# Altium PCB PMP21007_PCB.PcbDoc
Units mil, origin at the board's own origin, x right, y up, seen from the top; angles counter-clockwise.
Board outline 3407.03 x 1007.03 mil, 2 copper layers (Top Layer, Bottom Layer), stack 62 mil thick; 21 components, 11 nets, 43 pads, 0 vias.
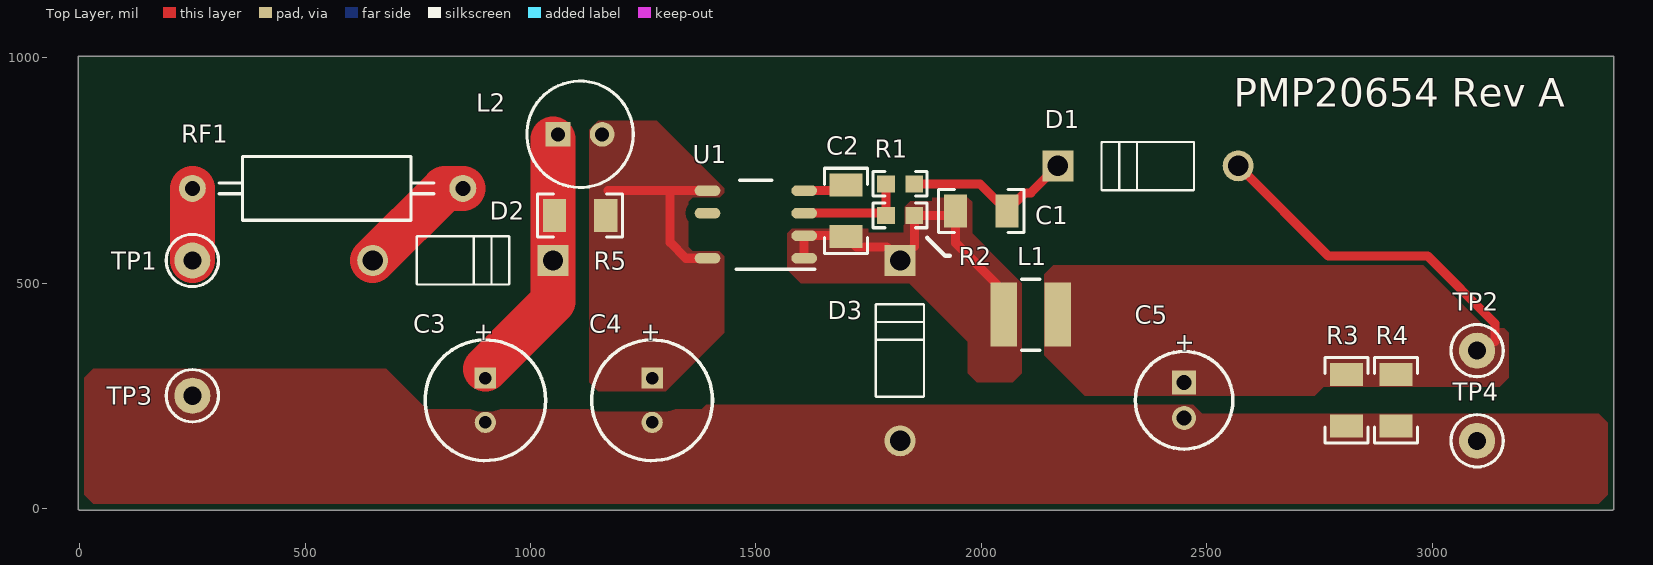
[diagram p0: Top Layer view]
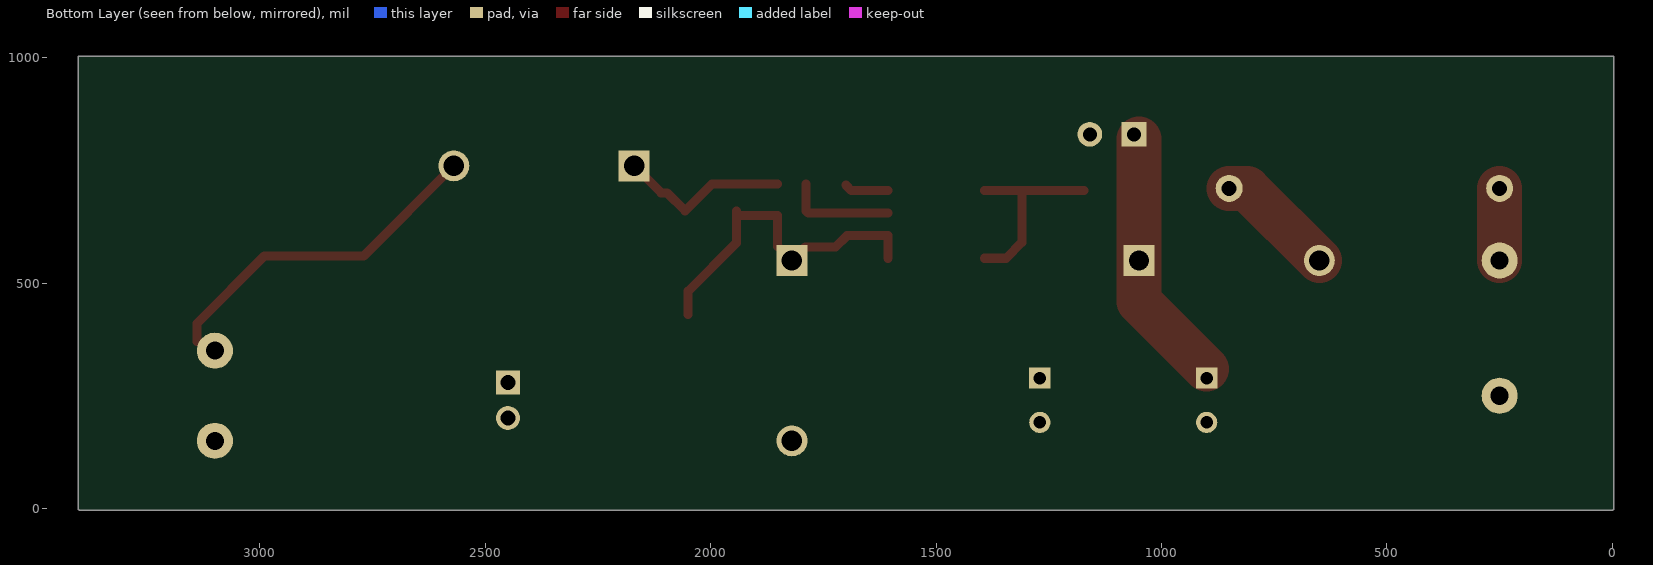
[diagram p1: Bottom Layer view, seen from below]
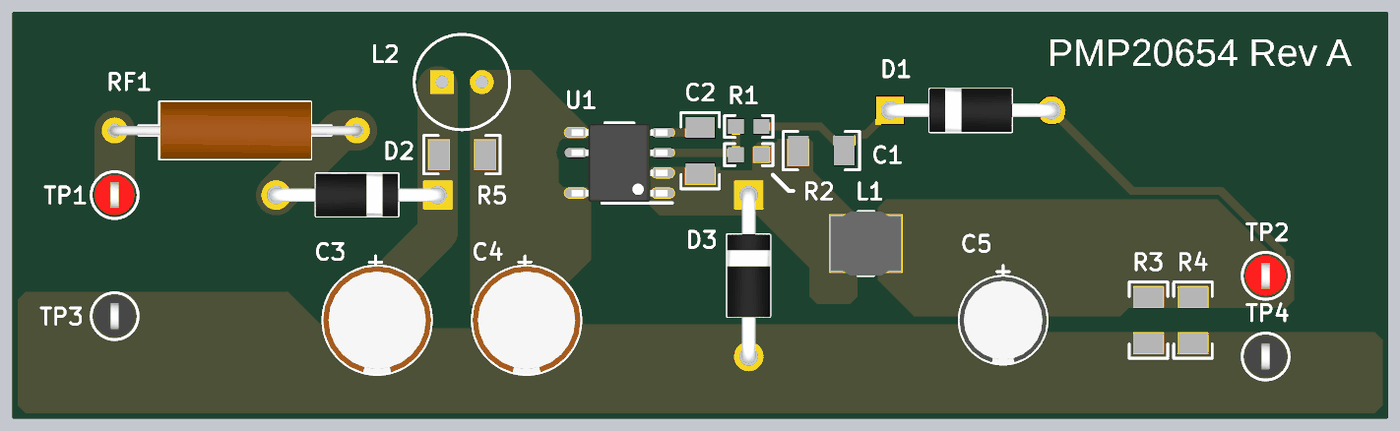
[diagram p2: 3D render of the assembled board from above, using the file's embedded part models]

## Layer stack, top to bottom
Top Solder: solder mask 0.4, Solder Resist, Dk 3.5
Top Layer: signal copper 1.4
Dielectric1: core 59.2, FR-4, Dk 4.8
Bottom Layer: signal copper 1.4
Bottom Solder: solder mask 0.4, Solder Resist, Dk 3.5

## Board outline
0,-3.52 cw(c0,0) -3.51,0 -3.51,1000 cw(c0,1000) 0,1003.51 3400,1003.51 cw(c3400,1000) 3403.51,1000 3403.51,0 cw(c3400,0) 3400,-3.52

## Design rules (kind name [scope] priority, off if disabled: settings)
AcuteAngle [All] p1: minimum=4.50000000000000E+0001 checktracksonly=FALSE
AssemblyTestPointUsage [All] p1: valid=2
Clearance Clearance_2 [InNetClass('HV') vs Not InNetClass('HV')] p1: gap=45
Clearance Clearance_Keepouts [((IsTrack Or IsArc) And Not InPoly) And IsFree and IsKeepOut vs ((IsTrack Or IsArc) And Not InPoly) And IsFree and IsKeepOut] p2: gap=0
Clearance Clearance_BoardEdge_MountingHoles [OnCopper and InComponentClass('Mounting Holes') vs IsKeepOut] p3: gap=40
Clearance Clearance_BoardEdge_Poly [OnCopper and InPoly vs IsKeepOut] p4: gap=25
Clearance Clearance_BoardEdge [OnCopper and Not InComponentClass('Logo') and not InComponentClass('FiducialMark') and not InRegion(1000,500,4000,800) and Not IsKeepout vs IsKeepOut] p5: gap=75
Clearance Clearance_Poly [InPolygon] p6: gap=20
Clearance [All] p7: gap=7.87
ComponentClearance ComponentClearance_MountingHoles_FiducialMarks [InComponentClass('Mounting Holes') vs InComponentClass('FiducialMark')] p1: gap=20 collisioncheckmode=3 verticalgap=10 showdistances=FALSE
ComponentClearance ComponentClearance_Shunt [InComponentClass('Header') vs InComponentClass('Shunt')] p2: gap=0 collisioncheckmode=3 verticalgap=0 showdistances=FALSE
ComponentClearance ComponentClearance_Logo [InComponentClass('Logo')] p3: gap=5 collisioncheckmode=3 verticalgap=10 showdistances=FALSE
ComponentClearance ComponentClearance_ScrewToNut [(HasFootprint('NY PMS 440 0025 PH')) vs (HasFootprint('Keystone_1902C'))] p4: gap=20 collisioncheckmode=3 verticalgap=100000 showdistances=FALSE
ComponentClearance ComponentClearance_MountingHoles [InComponentClass('Mounting Holes')] p5: gap=20 collisioncheckmode=3 verticalgap=10 showdistances=FALSE
ComponentClearance ComponentClearance_SmallPassives [HasFootprint('0201*') or HasFootprint('0402*') or HasFootprint('0508') or HasFootprint('0603*') or HasFootprint('0612') or HasFootprint('0805*') or HasFootprint('0815*') or HasFootprint('0830*') or HasFootprint('1206*') or HasFootprint('1210*') or HasFootprint('1808*') or HasFootprint('1812*') or HasFootprint('1825*') or HasFootprint('2010*') or HasFootprint('2220*') or HasFootprint('2225*') or HasFootprint('2512*') or HasFootprint('2728*') or HasFootprint('3518*') vs HasFootprint('0201*') or HasFootprint('0402*') or HasFootprint('0508') or HasFootprint('0603*') or HasFootprint('0612') or HasFootprint('0805*') or HasFootprint('0815*') or HasFootprint('0830*') or HasFootprint('1206*') or HasFootprint('1210*') or HasFootprint('1808*') or HasFootprint('1812*') or HasFootprint('1825*') or HasFootprint('2010*') or HasFootprint('2220*') or HasFootprint('2225*') or HasFootprint('2512*') or HasFootprint('2728*') or HasFootprint('3518*')] p6: gap=20 collisioncheckmode=3 verticalgap=20 showdistances=FALSE
ComponentClearance ComponentClearance_THtoSMT [IsThruComponent vs IsSMTComponent] p7: gap=10 collisioncheckmode=3 verticalgap=10 showdistances=FALSE
ComponentClearance ComponentClearance_THtoTH [IsThruComponent vs IsThruComponent] p8: gap=10 collisioncheckmode=3 verticalgap=10 showdistances=FALSE
ComponentClearance [All] p9: gap=10 collisioncheckmode=3 verticalgap=10 showdistances=FALSE
DiffPairsRouting [All] p1: maxlimit=100 minlimit=10 mostfreqgap=10 toplayer_minwidth=15 toplayer_maxwidth=15 toplayer_prefwidth=15 bottomlayer_minwidth=15 bottomlayer_maxwidth=15 bottomlayer_prefwidth=15 maxuncoupledlength=1000
FabricationTestPointUsage TestPointUsage [All] p1: valid=2 allowmultiple=FALSE
FabricationTestpoint Testpoint [All] p1: side=3 testpointundercomponent=TRUE minsize=40 maxsize=100 preferedsize=60 minholesize=0 maxholesize=40 preferedholesize=32 testpointgrid=1 allowsidetop=TRUE allowsidebottom=TRUE usegrid=TRUE gridtolerance=0.01
FanoutControl Fanout_LCC [IsLCC] p1: bgadir=Out bgaviamode=Centered fanoutstyle=Auto fanoutdirection=Alternating viagrid=1 // Fanout_LCC (Default Rule)
FanoutControl Fanout_BGA [IsBGA] p2: bgadir=Out bgaviamode=Centered fanoutstyle=Auto fanoutdirection=Alternating viagrid=1 // Fanout_BGA (Default Rule)
FanoutControl Fanout_Default [All] p4: bgadir=Out bgaviamode=Centered fanoutstyle=Auto fanoutdirection=Alternating viagrid=1 // Fanout_Default (Default Rule)
FanoutControl Fanout_Small [(CompPinCount < 5)] p5: bgadir=Out bgaviamode=Centered fanoutstyle=Auto fanoutdirection=OutThenIn viagrid=1 // Fanout_Small (Default Rule)
Height [All] p1: minheight=0 maxheight=3000 prefheight=500
HoleSize [All] p1: absolutevalues=TRUE maxlimit=251 minlimit=7 maxpercent=80.000 minpercent=20.000
MinimumAnnularRing MinimumAnnularRing_ThermalPadVias [IsVia and InAnyComponent] p1: minimumring=5.91
MinimumAnnularRing [All] p2: minimumring=4.9
MinimumSolderMaskSliver MinimumSolderMaskSliver_Logo [InComponentClass('Logo') vs InComponentClass('Logo')] p1: minsoldermaskwidth=0.7
MinimumSolderMaskSliver [All] p2: minsoldermaskwidth=2
PlaneConnect [All] p1: planeconnectstyle=Relief reliefexpansion=10 reliefentries=4 reliefconductorwidth=10 reliefairgap=10
PolygonConnect PolygonConnect_10 [All vs IsNamedPolygon('GND') Or  IsNamedPolygon('C1_2') Or  IsNamedPolygon('C4_1') Or  IsNamedPolygon('C5_1')] p1: connectstyle=Direct reliefconductorwidth=10 reliefentries=4 polygonreliefangle="90 Angle" airgapwidth=10
PolygonConnect PolygonConnect_9 [All vs IsNamedPolygon('C11_1') Or  IsNamedPolygon('Vin') Or  IsNamedPolygon('Vin') Or  IsNamedPolygon('5V') Or  IsNamedPolygon('D6_2') Or  IsNamedPolygon('Q3_3') Or  IsNamedPolygon('GND2') Or  IsNamedPolygon('GND2') Or  IsNamedPolygon('GND') Or  IsNamedPolygon('Q3_4') Or  IsNamedPolygon('12V5') Or  IsNamedPolygon('GND') Or  IsNamedPolygon('12V5') Or  IsNamedPolygon('D3_1')] p2: connectstyle=Direct reliefconductorwidth=10 reliefentries=4 polygonreliefangle="90 Angle" airgapwidth=10
PolygonConnect PolygonConnect_8 [All vs IsNamedPolygon('C11_1') Or  IsNamedPolygon('Vin') Or  IsNamedPolygon('12V5') Or  IsNamedPolygon('Q3_3') Or  IsNamedPolygon('GND2') Or  IsNamedPolygon('GND2') Or  IsNamedPolygon('5V') Or  IsNamedPolygon('Q3_4') Or  IsNamedPolygon('12V5')] p3: connectstyle=Direct reliefconductorwidth=10 reliefentries=4 polygonreliefangle="90 Angle" airgapwidth=10
PolygonConnect PolygonConnect_7 [All vs IsNamedPolygon('GND2') Or  IsNamedPolygon('GND2') Or  IsNamedPolygon('5V') Or  IsNamedPolygon('12V5') Or  IsNamedPolygon('12V5') Or  IsNamedPolygon('C11_1')] p4: connectstyle=Direct reliefconductorwidth=10 reliefentries=4 polygonreliefangle="90 Angle" airgapwidth=10
PolygonConnect PolygonConnect_6 [All vs IsNamedPolygon('GND2') Or  IsNamedPolygon('SGND') Or  IsNamedPolygon('GND1') Or  IsNamedPolygon('C901_1') Or  IsNamedPolygon('SGND') Or  IsNamedPolygon('GND2') Or  IsNamedPolygon('GND1')] p5: connectstyle=Direct reliefconductorwidth=10 reliefentries=4 polygonreliefangle="90 Angle" airgapwidth=10
PolygonConnect PolygonConnect_5 [All vs IsNamedPolygon('GND1') Or  IsNamedPolygon('GND1')] p6: connectstyle=Direct reliefconductorwidth=10 reliefentries=4 polygonreliefangle="90 Angle" airgapwidth=10
PolygonConnect PolygonConnect_4 [All vs IsNamedPolygon('C21_1') Or  IsNamedPolygon('C5_1') Or  IsNamedPolygon('C12_2') Or  IsNamedPolygon('C2_2') Or  IsNamedPolygon('C13_1') Or  IsNamedPolygon('C28_1') Or  IsNamedPolygon('C6_1') Or  IsNamedPolygon('GND') Or  IsNamedPolygon('GND2') Or  IsNamedPolygon('C14_1') Or  IsNamedPolygon('C13_1') Or  IsNamedPolygon('Q1_3') Or  IsNamedPolygon('C14_1') Or  IsNamedPolygon('C5_1') Or  IsNamedPolygon('GND2') Or  IsNamedPolygon('C28_1') Or  IsNamedPolygon('D5_2') Or  IsNamedPolygon('D6_2') Or  IsNamedPolygon('D2_1') Or  IsNamedPolygon('C12_2') Or  IsNamedPolygon('D2_1') Or  IsNamedPolygon('C4_1') Or  IsNamedPolygon('C4_1') Or  IsNamedPolygon('C2_2') Or  IsNamedPolygon('GND') Or  IsNamedPolygon('C33_1') Or  IsNamedPolygon('C9_1')] p7: connectstyle=Direct reliefconductorwidth=10 reliefentries=4 polygonreliefangle="90 Angle" airgapwidth=10
PolygonConnect PolygonConnect_3 [All vs IsNamedPolygon('C28_1') Or  IsNamedPolygon('C12_2') Or  IsNamedPolygon('C28_1') Or  IsNamedPolygon('C9_1') Or  IsNamedPolygon('D5_2') Or  IsNamedPolygon('C12_2') Or  IsNamedPolygon('C2_2') Or  IsNamedPolygon('C14_1') Or  IsNamedPolygon('C4_1') Or  IsNamedPolygon('C14_1') Or  IsNamedPolygon('D6_2') Or  IsNamedPolygon('GND2') Or  IsNamedPolygon('Q1_3') Or  IsNamedPolygon('C5_1') Or  IsNamedPolygon('D2_1') Or  IsNamedPolygon('C4_1') Or  IsNamedPolygon('C13_1') Or  IsNamedPolygon('C5_1') Or  IsNamedPolygon('C13_1') Or  IsNamedPolygon('C33_1') Or  IsNamedPolygon('D2_1') Or  IsNamedPolygon('GND') Or  IsNamedPolygon('GND') Or  IsNamedPolygon('GND2') Or  IsNamedPolygon('C2_2') Or  IsNamedPolygon('C6_1') Or  IsNamedPolygon('C21_1')] p8: connectstyle=Direct reliefconductorwidth=10 reliefentries=4 polygonreliefangle="90 Angle" airgapwidth=10
PolygonConnect PolygonConnect_2 [All vs IsNamedPolygon('C21_1') Or  IsNamedPolygon('C4_1') Or  IsNamedPolygon('D5_2') Or  IsNamedPolygon('C5_1') Or  IsNamedPolygon('C14_1') Or  IsNamedPolygon('C13_1') Or  IsNamedPolygon('C4_1') Or  IsNamedPolygon('C33_1') Or  IsNamedPolygon('C12_2') Or  IsNamedPolygon('D2_1') Or  IsNamedPolygon('C2_2') Or  IsNamedPolygon('C28_1') Or  IsNamedPolygon('C12_2') Or  IsNamedPolygon('D2_1') Or  IsNamedPolygon('C5_1') Or  IsNamedPolygon('Q1_3') Or  IsNamedPolygon('GND') Or  IsNamedPolygon('D6_2') Or  IsNamedPolygon('C6_1') Or  IsNamedPolygon('C2_2') Or  IsNamedPolygon('C14_1') Or  IsNamedPolygon('C28_1') Or  IsNamedPolygon('C13_1') Or  IsNamedPolygon('C9_1') Or  IsNamedPolygon('GND')] p9: connectstyle=Direct reliefconductorwidth=10 reliefentries=4 polygonreliefangle="90 Angle" airgapwidth=10
PolygonConnect PolygonConnect_1 [All vs IsNamedPolygon('C28_1') Or  IsNamedPolygon('D5_2') Or  IsNamedPolygon('C5_1') Or  IsNamedPolygon('C5_1') Or  IsNamedPolygon('D2_1') Or  IsNamedPolygon('C21_1') Or  IsNamedPolygon('C9_1') Or  IsNamedPolygon('C4_1') Or  IsNamedPolygon('C14_1') Or  IsNamedPolygon('C28_1') Or  IsNamedPolygon('C6_1') Or  IsNamedPolygon('C12_2') Or  IsNamedPolygon('C33_1') Or  IsNamedPolygon('C4_1') Or  IsNamedPolygon('C13_1') Or  IsNamedPolygon('C12_2') Or  IsNamedPolygon('D6_2') Or  IsNamedPolygon('C2_2') Or  IsNamedPolygon('C14_1') Or  IsNamedPolygon('D2_1') Or  IsNamedPolygon('C2_2') Or  IsNamedPolygon('C13_1')] p10: connectstyle=Direct reliefconductorwidth=10 reliefentries=4 polygonreliefangle="90 Angle" airgapwidth=10
PolygonConnect [All] p11: connectstyle=Relief reliefconductorwidth=10 reliefentries=4 polygonreliefangle="90 Angle" airgapwidth=10
RoutingVias ThermalPadVias [IsVia and InAnyComponent] p1: holewidth=7.87 width=19.68 viastyle="Through Hole" minholewidth=7.87 minwidth=19.68 maxholewidth=12.99 maxwidth=23.62
RoutingVias [All] p2: holewidth=16 width=34 viastyle="Through Hole" minholewidth=7.87 minwidth=20 maxholewidth=40 maxwidth=65
SilkToBoardRegionClearance [Not ((IsComment or IsDesignator) And (Hide <> 'False')) and not InRegion(1000,500,4000,800)] p1:
SilkToSilkClearance SilkToSilkClearance_Pb-FreeLogo [(HasFootprint('Pb-Free_Overlay_Medium') OR HasFootprint('Pb-Free_Overlay_Small')) vs (HasFootprint('Pb-Free_Overlay_Medium') OR HasFootprint('Pb-Free_Overlay_Small'))] p1: silktosilkclearance=0
SilkToSilkClearance [All] p2: silktosilkclearance=1
SilkToSolderMaskClearance "Silk to Solder Mask Opening" [All] p1: minsilkscreentomaskgap=1 clearancetoexposedcopper=FALSE
SolderMaskExpansion [All] p1: expansion=1.97
Width [All] p1: maxlimit=100 minlimit=6 preferedwidth=10 checkconnectedcopper=TRUE
14 further rules are at their usual default settings.

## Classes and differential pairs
net class HV: NC NetC1_1 NetC1_2 NetC2_1 NetC3_1 NetC4_1 NetD2_2 NetR1_1 NetRF1_2

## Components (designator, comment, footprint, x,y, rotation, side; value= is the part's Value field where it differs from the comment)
C1 "12065C104JAT2A" 1206 2000,660 r180 top
C2 "12065C223KAT2A" 1206 1700,660 r270 top
C3 "UPS2E010MED1TD" Chemi-Con_630x1150 900,240 r270 top
C4 "UPS2E010MED1TD" Chemi-Con_630x1150 1270,240 r270 top
C5 "ECA-1CHG470" NHG_500x1100 2450,240 r270 top
D1 "MUR160GP-TP" DO-41 2370,760 r0 top
D2 "1N4004" DO-41 850,550 r180 top
D3 "MUR160GP-TP" DO-41 1820,350 r270 top
L1 "SRN4018-221M" SRN4018 2110,430 r0 top
L2 "7447462102" WE-TI_5075 1110,830 r0 top
R1 "RC0603FR-07110KL" 0603 1820,720 r0 top
R2 "CRCW060310K0FKEA" 0603 1820,650 r180 top
R3 "CRCW120612K0JNEA" 1206 2810,240 r90 top
R4 "CRCW120612K0JNEA" 1206 2920,240 r90 top
R5 "CRCW12064R70JNEA" 1206 1110,650 r0 top
RF1 "FKN1WSJR-52-4R7" RESAD1524W55L900D150 550,710 r180 top
TP1 "5000" Keystone5000 250,550 r0 top
TP2 "5000" Keystone5000 3100,350 r0 top
TP3 "5001" Keystone5001 250,250 r0 top
TP4 "5001" Keystone5001 3100,150 r0 top
U1 "UCC28880DR" D0007A_N 1500,630 r180 top

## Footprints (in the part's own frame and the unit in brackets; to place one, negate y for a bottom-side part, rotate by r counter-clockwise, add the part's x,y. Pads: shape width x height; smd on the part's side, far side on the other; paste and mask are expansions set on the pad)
0603 [mm] "0603 from SM-752 data"
  rect 1x0.95 smd: 1(-0.8,0) 2(0.8,0)
  silkscreen extent -1.52,-0.69 1.52,0.69, body extent -0.87,-0.47 0.87,0.47, height 1
1206 [mm] "1206 from SM-752 data"
  rect 1.3x1.85 smd: 1(-1.45,0) 2(1.45,0)
  silkscreen extent -2.4,-1.21 2.4,1.21, body extent -1.7,-0.9 1.7,0.9, height 1.35
Chemi-Con_630x1150 [mm] "TH, 2-Leads, Dia 6.3mm, Pin Spacing 2.5mm"
  rect 1.2x1.2 hole 0.7: 1(-1.25,0)
  round 1.2 hole 0.7: 2(1.25,0)
  silkscreen extent -3.4,-3.4 3.4,3.4, body extent -3.4,-3.4 3.41,3.4, height 13.01
D0007A_N [mm] "SOIC, 7-Leads, Body 4.9x3.9mm, Pitch 1.27mm, IPC Medium Density"
  oval 1.45x0.6 smd: 1(-2.725,1.905) 2(-2.725,0.635) 3(-2.725,-0.635) 4(-2.725,-1.905) 5(2.725,-1.905) 6(2.725,-0.635) 8(2.725,1.905)
  silkscreen extent -3.32,-2.5 1.1,2.52, body extent -3.01,-2.45 3.01,2.45, height 1.75
DO-41 [mm] "diode"
  rect 1.75x1.75 hole 1.15: 1(-5.08,0)
  round 1.75 hole 1.15: 2(5.08,0)
  silkscreen extent -2.62,-1.37 2.59,1.35, body extent -5.51,-1.36 5.51,1.36, height 2.72
Keystone5000 [mil] "For Keystone 500x miniature loop terminals"
  round 80 hole 40: 1(0,0)
  silkscreen extent -58,-58 58,58, body extent -49,-49 49,49, height 182
Keystone5001 [mil] "For Keystone 500x miniature loop terminals"
  round 80 hole 40: 1(0,0)
  silkscreen extent -58,-58 58,58, body extent -49,-49 49,49, height 182
NHG_500x1100 [mm] "TH, 2-Leads, Dia 5mm,  Lead Spacing 2mm"
  rect 1.35x1.35 hole 0.85: 1(-1,0)
  round 1.35 hole 0.85: 2(1,0)
  silkscreen extent -2.75,-2.75 2.75,2.75, body extent -2.73,-2.75 2.75,2.75, height 12.51
RESAD1524W55L900D150 [mil]
  round 60 hole 33.46: 1(-300,0) 2(300,0)
  silkscreen extent -236,-71 240,71, body extent -312,-71 312,71, height 141
SRN4018 [mm] "SMD, 2-Leads, Body 4.2x4.2mm, Pitch 3.05mm"
  rect 1.5x3.6 smd: 1(-1.525,0) 2(1.525,0)
  silkscreen extent -0.5,-2 0.5,2, body extent -2.2,-2 2.2,2, height 1.8
WE-TI_5075 [mm] "Wurth WE-TI 5075"
  rect 1.4x1.4 hole 0.787: 1(-1.25,0)
  round 1.4 hole 0.787: 2(1.25,0)
  silkscreen extent -3,-3 3,3, body extent -3,-3 3,3, height 8.5

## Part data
C1: "CAP, CERM, 0.1uF, 50V, +/-5%, X7R, 1206"
C2: "CAP, CERM, 0.022uF, 50V, +/-10%, X7R, 1206"
C3 C4: library part ELXZ100ELL221MFB5D, "1µF 250V Aluminum Capacitors Radial, Can 2000 Hrs @ 105°C"
C5: "CAP, AL, 47 µF, 16 V, +/- 20%, TH"
D1 D3: library part 1N4007, "Diode Standard 600V 1A Through Hole DO-41"
D2: library part 1N4007, "Diode Standard 400V 1A Through Hole DO-41"
L1: library part SRN4018-151M, "220µH Shielded Wirewound Inductor 280mA 3.552 Ohm Max Nonstandard"
L2: "Inductor, Unshielded Drum Core, Ferrite, 1 mH, 0.25 A, 4.38 ohm, TH"
R1: "RES, 110 k, 1%, 0.1 W, 0603"
R2: "RES, 10.0k ohm, 1%, 0.1W, 0603"
R3 R4: "RES, 12k ohm, 5%, 0.25W, 1206"
R5: "RES, 4.7, 5%, 0.25 W, 1206"
RF1: "RES, 4.7 ohm, 5%, 1W, Fusible, TH"
TP1 TP2: "Test Point, Miniature, Red, TH"
TP3 TP4: "Test Point, Miniature, Black, TH"
U1: "700-V Lowest Quiescent Current Off-Line Switcher, D0007A (SOIC-7)"

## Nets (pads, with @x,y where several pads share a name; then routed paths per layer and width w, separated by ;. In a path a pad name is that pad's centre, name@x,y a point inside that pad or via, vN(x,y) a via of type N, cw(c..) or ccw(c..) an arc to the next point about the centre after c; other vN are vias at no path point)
GND: C3.2 C4.2 C5.2 D3.2 R3.1 R4.1 TP3.1 TP4.1
NC: U1.6
NetC1_1: C1.1 D1.1 R1.2 | length 384.8
  Top Layer w20: R1.2 1997.09,720 C1.1 2097.09,700 2110,700 D1.1
NetC1_2: C1.2 C2.2 D3.1 L1.1 R2.1 U1.1 U1.2 | length 754.3
  Top Layer w20: U1.1 U1.2 1697.91,605 C2.2 1722.91,580 1790,580 D3.1 1851.5,581.5 R2.1 C1.2@1932.91,650 ; C1.2 1942.91,589.22 2049.96,482.18 L1.1
NetC2_1: C2.1 U1.4 | length 97.7
  Top Layer w20: U1.4 1687.91,705 C2.1
NetC3_1: C3.1 D2.1 L2.1 R5.1 | length 571.9
  Top Layer w100: C3.1@900,309.41 1050,459.41 D2.1 L2.1@1050,819.21
NetC4_1: C4.1 L2.2 R5.2 U1.5 U1.8 | length 433.5
  Top Layer w20: 1172.09,705 1310,705 ; U1.8 1345,555 1310,590 1310,626.5 1309.17,627.33 1309.17,683.5 1310,684.33 1310,705 ; U1.5 1310,705
NetC5_1: C5.1 D1.2 L1.2 R3.2 R4.2 TP2.1 | length 755
  Top Layer w20: D1.2 2770,560 2990,560 3140,410 3140,370
NetD2_2: D2.2 RF1.1 | length 266.3
  Top Layer w100: D2.2 810,710 RF1.1
NetR1_1: R1.1 R2.2 U1.3 | length 243.3
  Top Layer w20: U1.3 1783.5,655 1788.5,660 R1.1
NetRF1_2: RF1.2 TP1.1 | length 160
  Top Layer w100: TP1.1 RF1.2

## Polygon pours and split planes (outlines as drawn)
GND on Top Layer "GND" (solid, remove dead copper, pour order 6): 30,310 10,290 10,30 30,10 130,10 3370,10 3390,30 3390,90 3390,190 3370,210 3350,210 2490,210 2470,230 2460,230 1390,230 1380,220 1340,220 770,220 680,310
NetC5_1 on Top Layer "C5_1" (solid, remove dead copper, pour order 4): 2160,540 2140,520 2140,480 2140,340 2230,250 2260,250 2740,250 2760,270 2980,270 3150,270 3170,290 3170,310 3170,390 3160,400 3120,400 2980,540
NetC1_2 on Top Layer "C1_2" (solid, remove dead copper, pour order 2): 1580,620 1570,610 1570,530 1580,520 1600,500 1790,500 1840,500 1970,370 1970,300 1990,280 2070,280 2090,300 2090,380 2090,500 2050,540 1980,610 1980,680 1970,690 1890,690 1851.3,690 1830,668.7 1830,631.3 1830,630 1820,620
NetC4_1 on Top Layer "C4_1" (solid, remove dead copper, pour order 0): 1150,860 1130,840 1130,720 1130,620 1130,520 1130,280 1150,260 1300,260 1420,380 1430,390 1430,559.29 1419.29,570 1400,570 1360,570 1350,580 1350,660 1350,680 1360,690 1370,690 1420,690 1430,700 1430,710 1280,860

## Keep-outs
Keep-Out Layer:
  text ".Layer_Name" at 577,-858.49 h60

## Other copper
Top Layer:
  text ".Layer_Name" at 577,-858.49 h60
Bottom Layer:
  text ".Layer_Name" at 577,-858.49 h60

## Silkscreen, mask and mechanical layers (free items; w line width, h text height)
Top Overlay:
  lines w10: 1880,600 1920,560 1930,560
  text "PMP20654 Rev A" at 2560,870 h108.27
  text ".Layer_Name" at 577,-858.49 h60
Bottom Overlay:
  text ".Layer_Name" at 577,-858.49 h60
Top Paste:
  text ".Layer_Name" at 577,-858.49 h60
Bottom Paste:
  text ".Layer_Name" at 577,-858.49 h60
Top Solder:
  text ".Layer_Name" at 577,-858.49 h60
  text ".Layer_Name" at 577,-858.49 h60
Bottom Solder:
  text ".Layer_Name" at 577,-858.49 h60
Drill Guide:
  text ".Layer_Name" at 577,-858.49 h60
M1 Board Outline:
  lines w7: 0,0 0,1000 ; 0,0 3400,0 ; 0,0 0,1000 ; 0,0 3400,0 ; 0,1000 3400,1000 ; 0,1000 3400,1000 ; 3400,0 3400,1000 ; 3400,0 3400,1000
  text ".Layer_Name" at 577,-858.49 h60
M2 Board Dimensions:
  rectangle: 0,-275 125,-150
  rectangle: 125,-400 500,-275
  lines w7: 0,-275 1000,-275 ; 125,-400 125,-150 ; 250,-400 250,-150 ; 500,-400 500,-150 ; 750,-400 750,-150 ; 0,-400 1000,-400 1000,-150 0,-150 0,-400
  text ".Layer_Name" at 577,-858.49 h60
M3 3D STEP Top:
  text ".Layer_Name" at 577,-858.49 h60
M4 3D STEP Bottom:
  text ".Layer_Name" at 577,-858.49 h60
M5 Assembly Top:
  lines w10: -292,-930.17 6308,-930.17 ; -292,-726.83 6310,-726.83 ; -292,-523.5 -292,-1133.5 3713,-1133.5 6310,-1133.5 6310,-523.5 -291.5,-523.5 -291.5,-1133.5 1284,-1133.5 ; 2173,-1133.5 2173,-523.5 ; 3440,-726.83 3440,-523.5 ; 4280,-726.83 4280,-523.5 ; 4902,-1140 4902,-937.17
  text "COMPONENTS MARKED 'DNP' SHOULD NOT BE POPULATED." at 1153.5,-318.5 h60
  text "ASSEMBLY VARIANT:" at 1153,-434 h60
  text ".VariantName" at 2189,-434 h60
  text "PCB VIEWED FROM TOP SIDE" at -228.5,-655.67 h60
  text "BOARD #:" at 2248,-655.67 h60
  text ".PRJ_Number" at 2793.5,-655.67 h60
  text "REV:" at 3638,-655.67 h60
  text ".PCB_Rev" at 3929.5,-655.67 h60
  text "SVN REV:" at 4476,-655.67 h60
  text ".VersionControl_RevNumber" at 4982,-655.67 h60
  text "TID #:" at 2248,-859 h60
  text ".TID" at 2793.5,-859 h60
  text "PLOT NAME =" at -228.5,-1064.34 h60
  text ".plot_File_Name" at 577,-1064.34 h60
  text "GENERATED    :" at 2250,-1064.34 h60
  text ".Print_Date" at 3119.5,-1064.34 h60
  text ".Print_Time" at 3848.5,-1064.34 h60
  text "TEXAS INSTRUMENTS" at 5113,-1064.34 h60
M6 Assembly Bottom:
  lines w10: -292.5,-727.33 6309.5,-727.33 ; -290.5,-930.67 6309.5,-930.67 ; 1115.5,-1140.5 1115.5,-937.67 ; 1737.5,-727.33 1737.5,-524 ; 2577.5,-727.33 2577.5,-524 ; 3844.5,-1134 3844.5,-524 ; 4733.5,-1134 6309,-1134 6309,-524 -292.5,-524 -292.5,-1134 2304.5,-1134 6309.5,-1134 6309.5,-524
  text "COMPONENTS MARKED 'DNP' SHOULD NOT BE POPULATED." at 6102,-318 h60
  text ".VariantName" at 5058,-434 h60
  text "ASSEMBLY VARIANT:" at 6097,-434 h60
  text ".VersionControl_RevNumber" at 1035.5,-656.17 h60
  text "SVN REV:" at 1541.5,-656.17 h60
  text ".PCB_Rev" at 2088,-656.17 h60
  text "REV:" at 2379.5,-656.17 h60
  text ".PRJ_Number" at 3224,-656.17 h60
  text "BOARD #:" at 3769.5,-656.17 h60
  text "PCB VIEWED FROM BOTTOM SIDE" at 6246,-656.17 h60
  text ".TID" at 3224,-859.5 h60
  text "TID #:" at 3769.5,-859.5 h60
  text "TEXAS INSTRUMENTS" at 904.5,-1064.84 h60
  text ".Print_Time" at 2169,-1064.84 h60
  text ".Print_Date" at 2898,-1064.84 h60
  text "GENERATED    :" at 3767.5,-1064.84 h60
  text ".plot_File_Name" at 5440.5,-1064.84 h60
  text "PLOT NAME =" at 6246,-1064.84 h60
M9 Title Sheet:
  drawing of 57 lines, arcs and shapes, not listed
  text "1" at 739.84,8036.5 h70
  text "2" at 3235.5,8036.5 h70
  text "3" at 5724.84,8036.5 h70
  text "4" at 8231.51,8036.5 h70
  text "5" at 10730.5,8036.5 h70
  text "6" at 13235.5,8036.5 h70
  text "A" at -416.5,6893.5 h70
  text "A" at 14383.5,6893.5 h70
  text "B" at -416.5,4513.5 h70
  text "B" at 14383.5,4513.5 h70
  text "C" at -416.5,2138.5 h70
  text "C" at 14383.5,2138.5 h70
  text "PROJECT TITLE:" at 11343.5,277.5 h45
  text ".PRJ_Title" at 11393.5,144.17 h70
  text "DESIGNED FOR:" at 11343.5,-23.5 h45
  text ".PRJ_Customer" at 11393.5,-163.5 h70
  text "D" at -416.5,-231.5 h70
  text "D" at 14383.5,-231.5 h70
  text "FILE NAME:" at 11343.5,-323.5 h45
  text ".PCB_File_Name_No_Path" at 11393.5,-443.5 h70
  text "Texas Instruments (TI) and/or its licensors do not warrant the accuracy or completeness of this specification" at 6374,-605.34 h45
  text "ENGINEER:" at 11343.5,-613.5 h45
  text "LAYOUT BY:" at 12848.5,-613.5 h45
  text "or any information contained therein. TI and/or its licensors do not warrant that this design will meet" at 6329.01,-718 h45
  text ".PRJ_Engineer" at 11393.5,-768.49 h70
  text ".PCB_Layout" at 12899,-768.49 h70
  text "the specifications, will be suitable for your application or fit for any particular purpose, or will operate in" at 6329.01,-830.67 h45
  text ".Layer_Name" at 577,-858.49 h60
  text "ALTIUM DESIGNER VERSION:" at 12848.5,-923.5 h45
  text "an implementation. TI and/or its licensors do not warrant that the design is production worthy. You should" at 6329.01,-943.33 h45
  text "completely validate and test your design implementation to confirm the system functionality for your application." at 6374,-1056 h45
  text ".print_Scale" at 11393.5,-1056.83 h70
  text ".Application_BuildNumber" at 12899,-1056.83 h70
  text "1" at 739.84,-1263.5 h70
  text "2" at 3235.5,-1263.5 h70
  text "3" at 5724.84,-1263.5 h70
  text "4" at 8231.51,-1263.5 h70
  text "5" at 10730.5,-1263.5 h70
  text "6" at 13235.5,-1263.5 h70
M10 Fab Notes:
  drawing of 173 lines, arcs and shapes, not listed
  text "DESIGN INFORMATION" at 12378.02,6201 h60
  text "MIN. TRACK WIDTH:" at 11733.46,6021 h60
  text "10" at 12829.7,6021 h60
  text "MIL" at 12984.46,6021 h60
  text "MIN. CLEARANCE:" at 11733.46,5889 h60
  text "0.2" at 12769.7,5889 h60
  text "mm" at 12984.46,5889 h60
  text "MIN. VIA PAD SIZE:" at 11733.46,5757 h60
  text "20" at 12799.71,5757 h60
  text "MIL" at 12984.46,5757 h60
  text "0.05mm (2MIL)" at 12428.46,5615.29 h60
  text "MINIMUM ANNULAR RING" at 11404.23,5611 h60
  text "EXTERNAL" at 13136.46,5611 h60
  text "PER" at 11604.23,5493 h60
  text "IPC-D-275 CLASS 2 LEVEL C" at 11824.23,5493 h60
  text "MIL, HOLES" at 13312.46,5380.71 h60
  text "+/-" at 12920,5380 h60
  text "+/-" at 13774,5380 h60
  text "REGISTRATION TOLERANCES:" at 11404.23,5375 h60
  text "METAL" at 12604,5375 h60
  text "5" at 13180.2,5375 h60
  text "3" at 14013.2,5375 h60
  text "MIL" at 14129.46,5375 h60
  text "+/-" at 13774,5262 h60
  text "HOLE SIZE TOLERANCE (UNLESS OTHERWISE SPECIFIED):" at 11404.23,5257 h60
  text "3" at 14013.2,5257 h60
  text "MIL" at 14129.46,5257 h60
  text "MATERIAL:" at 11329.46,5047.54 h60
  text "FR-4 High Tg" at 12315.9,4907.21 h60
  text "FR-408" at 11750.46,4898.64 h60
  text "OTHER" at 13238.46,4898.64 h60
  text "X" at 12161,4895 h60
  text "62 MIL (1.6mm) +/-10%" at 12070.56,4735.92 h60
  text "THICKNESS:" at 11404.23,4731.64 h60
  text "X" at 11942.4,4731.64 h60
  text "OTHER" at 13355.46,4731.64 h60
  text "TOLERANCE:" at 11404.23,4573.64 h60
  text "X" at 12243.53,4573.64 h60
  text "ANSI IPC-6012 TYPE 3 CLASS 2" at 12430.48,4573.64 h60
  text "OTHER +/-" at 12430.46,4417.64 h60
  text "BOW & TWIST:" at 11404.23,4260.64 h60
  text "X" at 12243.53,4260.64 h60
  text "ANSI IPC-6012 TYPE 3 CLASS 2" at 12430.48,4260.64 h60
  text "OTHER +/-" at 12430.46,4102.13 h60
  text "DRILLING:" at 11329.46,3963.64 h60
  text "REFERENCE:" at 11404.23,3846.64 h60
  text "X" at 12052.46,3846.64 h60
  text "AS SHOWN" at 12239.46,3846.64 h60
  text "X" at 12953.46,3846.64 h60
  text "NC_DRILL FILES" at 13090.46,3846.64 h60
  text "PTH COPPER THICKNESS:" at 11404.23,3688.64 h60
  text "X" at 12534.46,3688.64 h60
  text "20-30 um" at 12671.46,3688.64 h60
  text "OTHER" at 13388.46,3688.64 h60
  text "BOARD FINISH:" at 11329.46,3529.64 h60
  text "SILKSCREEN:" at 11484.68,3411.64 h60
  text "X" at 12433.46,3411.64 h60
  text "TOP" at 12559.46,3411.64 h60
  text "X" at 12943.46,3411.64 h60
  text "BOTTOM" at 13070.46,3411.64 h60
  text "SILKSCREEN COLOR:" at 11484.68,3244.64 h60
  text "X" at 12432.42,3244.64 h60
  text "WHITE" at 12559.46,3244.64 h60
  text "OTHER" at 13070.46,3244.64 h60
  text "X" at 12563.42,3085.44 h60
  text "GREEN" at 12690.46,3085.44 h60
  text "OTHER" at 13308.46,3085.44 h60
  text "SOLDER RESIST COLOR:" at 11484.68,3074.64 h60
  text "X" at 12563.42,2915.44 h60
  text "MATTE" at 12690.46,2915.44 h60
  text "SEMI-GLOSS" at 13308,2914.8 h60
  text "IMMERSION GOLD (ENIG)" at 12390.46,2726.92 h60
  text "ENEPIG" at 13728,2723.64 h60
  text "SURFACE FINISH:" at 11329.46,2722.64 h60
  text "X" at 11480,2570 h60
  text "IMM. TIN/SILVER OR EQUIV" at 11659,2565.64 h60
  text "OTHER" at 13090.46,2565.64 h60
  text "ARRAY/PANEL:" at 11329.46,2386.64 h60
  text "CUT AND TRIM PER M1 BOARD OUTLINE" at 12390.46,2382.35 h60
  text "N.C. ROUTE" at 12390.46,2230.64 h60
  text "X" at 13069.46,2230.64 h60
  text "V. SCORE" at 13256.46,2230.64 h60
  text "CERTIFICATION:" at 11329.46,2093.64 h60
  text "MATERIALS AND WORKMANSHIP FOR ALL PCBS" at 12054.46,2093.64 h60
  text "TO MEET OR EXCEED THE REQUIREMENTS OF:" at 12054.46,1995.64 h60
  text "X" at 11680.96,1859.13 h60
  text "ANSI IPC-A-600F CLASS ->" at 11819.96,1859.13 h60
  text "X" at 13459.02,1859.13 h60
  text "2" at 13577.96,1859.14 h60
  text "1" at 13262.96,1857.64 h60
  text "3" at 13931.96,1857.64 h60
  text "X" at 12495.02,1699.64 h60
  text "RoHS" at 12631.96,1699.64 h60
  text "OTHER" at 13276.36,1699.64 h60
  text "PER ORDER" at 13673.42,1699.64 h60
  text "ALL BOARDS MUST MEET OR EXCEED UL94-V0 REQUIREMENTS." at 11357,1534 h60
  text "PCB MUST BEAR THE UL94V-0 UL REGISTERED MATERIAL ID NUMBER" at 11357,1414 h60
  text "ADDITIONAL REQUIREMENTS:" at 11329.46,1240.64 h60
  text "MICROSECTION:" at 11404.23,1125.64 h60
  text "YES" at 12309.96,1125.64 h60
  text "X" at 12590,970 h60
  text "REQUIRED" at 13171.46,969.49 h60
  text "BARE BOARD ELEC. TEST:" at 11404.23,966.64 h60
  text "NONE" at 12709.96,966.64 h60
  text "PER ORDER" at 13763.46,966.64 h60
  text ".Layer_Name" at 577,-858.49 h60
M11 Gerber Information:
  lines w10: -292,-930.17 6308,-930.17 ; -292,-726.83 6310,-726.83 ; -292,-523.5 -292,-1133.5 3713,-1133.5 6310,-1133.5 6310,-523.5 -291.5,-523.5 -291.5,-1133.5 1284,-1133.5 ; 2173,-1133.5 2173,-523.5 ; 3440,-726.83 3440,-523.5 ; 4280,-726.83 4280,-523.5 ; 4902,-1140 4902,-937.17
  text "ALL ARTWORK VIEWED FROM TOP SIDE" at -228.5,-655.67 h60
  text "BOARD #:" at 2248,-655.67 h60
  text ".PRJ_Number" at 2793.5,-655.67 h60
  text "REV:" at 3638,-655.67 h60
  text ".PCB_Rev" at 3929.5,-655.67 h60
  text "SVN REV:" at 4476,-655.67 h60
  text ".VersionControl_RevNumber" at 4982,-655.67 h60
  text "LAYER NAME =" at -228.5,-858.49 h60
  text "TID #:" at 2248,-859 h60
  text ".TID" at 2793.5,-859 h60
  text "PLOT NAME =" at -228.5,-1064.34 h60
  text ".plot_File_Name" at 577,-1064.34 h60
  text "GENERATED    :" at 2250,-1064.34 h60
  text ".Print_Date" at 3119.5,-1064.34 h60
  text ".Print_Time" at 3848.5,-1064.34 h60
  text "TEXAS INSTRUMENTS" at 5113,-1064.34 h60
M12 Stackup:
  drawing of 191 lines, arcs and shapes, not listed
  text "Layer" at 9790.34,7830 h60
  text "Name" at 10200.26,7830 h60
  text "Material" at 11130,7830 h60
  text "Thickness" at 11989.77,7830 h60
  text "Constant" at 12639.6,7830 h60
  text "Board Layer Stack" at 13209.46,7830 h60
  text "1" at 9790.34,7710 h60
  text "Top Overlay" at 10200.26,7710 h60
  text "2" at 9790.34,7590 h60
  text "Top Solder" at 10200.26,7590 h60
  text "Solder Resist" at 11130,7590 h60
  text "0.40mil" at 11989.77,7590 h60
  text "3.5" at 12639.6,7590 h60
  text "3" at 9790.34,7470 h60
  text "Top Layer" at 10200.26,7470 h60
  text "Copper" at 11130,7470 h60
  text "1.40mil" at 11989.77,7470 h60
  text "4" at 9790.34,7350 h60
  text "Dielectric1" at 10200.26,7350 h60
  text "FR-4" at 11130,7350 h60
  text "59.20mil" at 11989.77,7350 h60
  text "4.8" at 12639.6,7350 h60
  text "5" at 9790.34,7230 h60
  text "Bottom Layer" at 10200.26,7230 h60
  text "Copper" at 11130,7230 h60
  text "1.40mil" at 11989.77,7230 h60
  text "6" at 9790.34,7110 h60
  text "Bottom Solder" at 10200.26,7110 h60
  text "Solder Resist" at 11130,7110 h60
  text "0.40mil" at 11989.77,7110 h60
  text "3.5" at 12639.6,7110 h60
  text "7" at 9790.34,6990 h60
  text "Bottom Overlay" at 10200.26,6990 h60
  text ".Layer_Name" at 577,-858.49 h60
M13 Component Bodies Top:
  text ".Layer_Name" at 577,-858.49 h60
M14 Component Bodies Bottom:
  text ".Layer_Name" at 577,-858.49 h60
M15 Courtyards Top:
  text ".Layer_Name" at 577,-858.49 h60
M16 Courtyards Bottom:
  text ".Layer_Name" at 577,-858.49 h60
Drill Drawing:
  circle w10: c5348.9,3203.16 r22.14
  lines w10: 5326.76,2882.15 5371.04,2882.15 5371.04,2926.43 5326.76,2926.43 5326.76,2882.15 ; 5326.76,2981.77 5348.9,2992.84 5371.04,2981.77 5359.97,3003.91 5371.04,3026.05 5348.9,3014.98 5326.76,3026.05 5337.83,3003.91 5326.76,2981.77 ; 5326.76,3125.67 5371.04,3125.67 5348.9,3081.4 5326.76,3125.67 ; 5326.76,3291.71 5337.83,3291.71 5348.9,3280.64 5359.97,3291.71 5371.04,3291.71 5359.97,3302.78 5371.04,3313.85 5359.97,3313.85 5348.9,3324.92 5337.83,3313.85 5326.76,3313.85 5337.83,3302.78 5326.76,3291.71
  lines w12: 5286,2852.27 8398.94,2852.27 ; 5286,3350.38 8398.94,3350.38 ; 5601.63,2752.64 5601.63,3450 ; 5918.82,2752.64 5918.82,3450 ; 6540.56,2752.64 6540.56,3450 ; 6784.88,2752.64 6784.88,3450 ; 7145.22,2752.64 7145.22,3450 ; 7854.73,2752.64 7854.73,3450 ; 5286,2752.64 8398.94,2752.64 8398.94,3450 5286,3450 5286,2752.64
  text "Symbol" at 5345.77,3380.26 h72
  text "Quantity" at 5631.52,3380.26 h72
  text "Finished Hole Size" at 5948.7,3380.26 h72
  text "Plated" at 6570.45,3380.26 h72
  text "Hole Type" at 6814.77,3380.26 h72
  text "Drill Layer Pair" at 7175.11,3380.26 h72
  text "Hole Tolerance" at 7884.62,3380.26 h72
  text "4" at 5631.52,3280.64 h60
  text "27.56mil (0.700mm)" at 5948.7,3280.64 h60
  text "PTH" at 6570.45,3280.64 h60
  text "Round" at 6814.77,3280.64 h60
  text "Top Layer - Bottom Layer" at 7175.11,3280.64 h60
  text "2" at 5631.52,3181.02 h60
  text "31.00mil (0.787mm)" at 5948.7,3181.02 h60
  text "PTH" at 6570.45,3181.02 h60
  text "Round" at 6814.77,3181.02 h60
  text "Top Layer - Bottom Layer" at 7175.11,3181.02 h60
  text "4" at 5631.52,3081.4 h60
  text "33.46mil (0.850mm)" at 5948.7,3081.4 h60
  text "PTH" at 6570.45,3081.4 h60
  text "Round" at 6814.77,3081.4 h60
  text "Top Layer - Bottom Layer" at 7175.11,3081.4 h60
  text "4" at 5631.52,2981.77 h60
  text "40.00mil (1.016mm)" at 5948.7,2981.77 h60
  text "PTH" at 6570.45,2981.77 h60
  text "Round" at 6814.77,2981.77 h60
  text "Top Layer - Bottom Layer" at 7175.11,2981.77 h60
  text "6" at 5631.52,2882.15 h60
  text "45.28mil (1.150mm)" at 5948.7,2882.15 h60
  text "PTH" at 6570.45,2882.15 h60
  text "Round" at 6814.77,2882.15 h60
  text "Top Layer - Bottom Layer" at 7175.11,2882.15 h60
  text "20 Total" at 5631.52,2782.53 h60
  text ".Layer_Name" at 577,-858.49 h60
M17 Embedded Cavity:
  text ".Layer_Name" at 577,-858.49 h60
M18 Embedded Assembly:
  text ".Layer_Name" at 577,-858.49 h60
M19 Embedded Keepout:
  text ".Layer_Name" at 577,-858.49 h60

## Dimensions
0,-400 to 1000,-400 on M2 Board Dimensions
0,0 to 0,1003.51 on M2 Board Dimensions
0,0 to -3.51,0 on M2 Board Dimensions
